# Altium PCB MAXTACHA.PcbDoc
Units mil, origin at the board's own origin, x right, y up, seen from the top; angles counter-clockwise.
Board outline 4035.43 x 2603.97 mil, 2 copper layers (Top Layer, Bottom Layer); 27 components, 20 nets, 75 pads, 0 vias.
Unrouted connection lines stored in the file: 14.
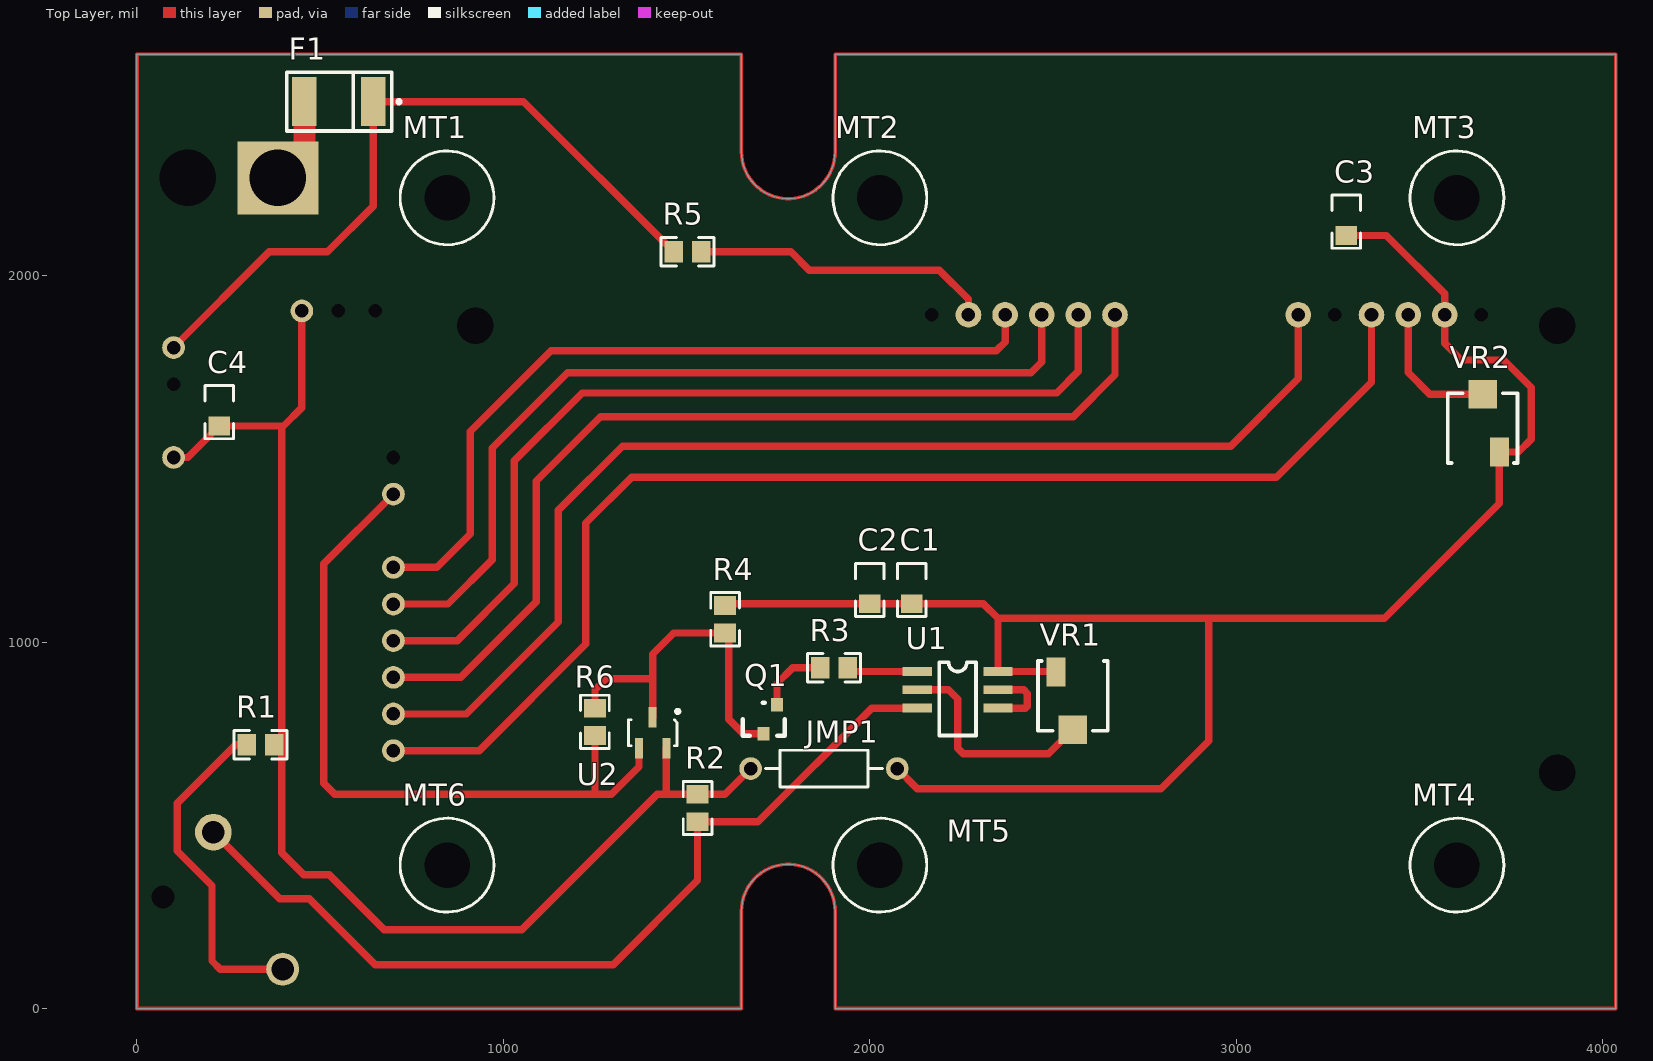
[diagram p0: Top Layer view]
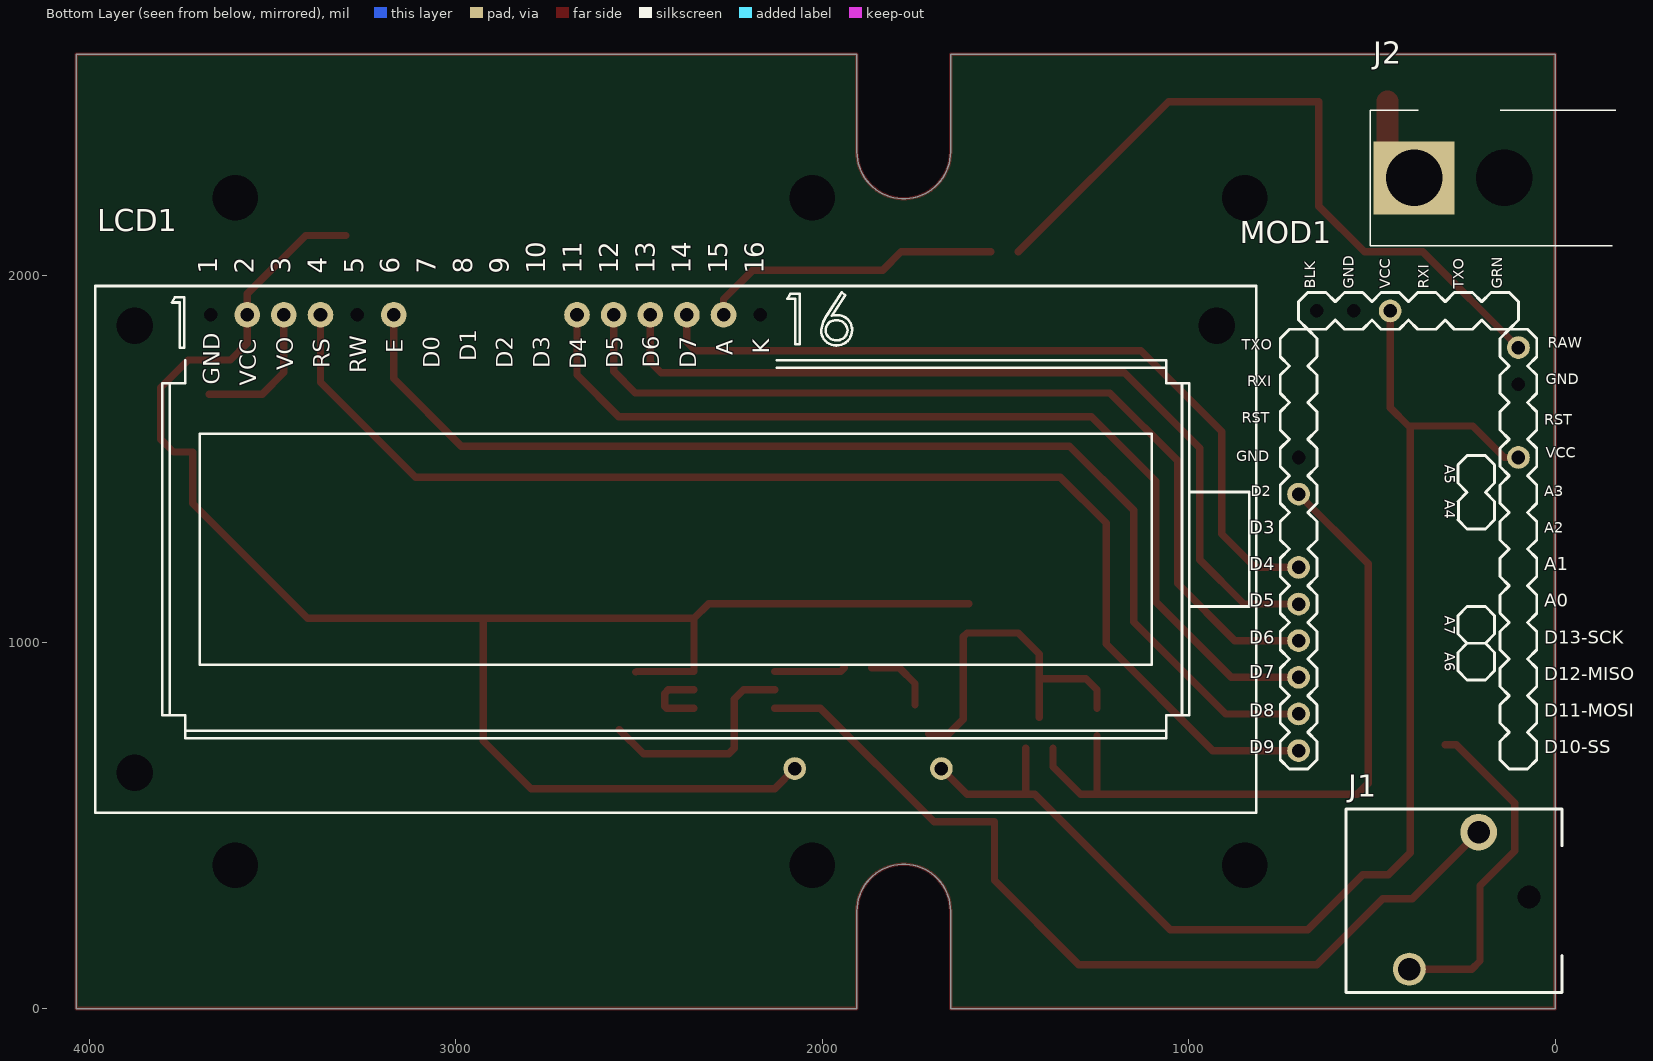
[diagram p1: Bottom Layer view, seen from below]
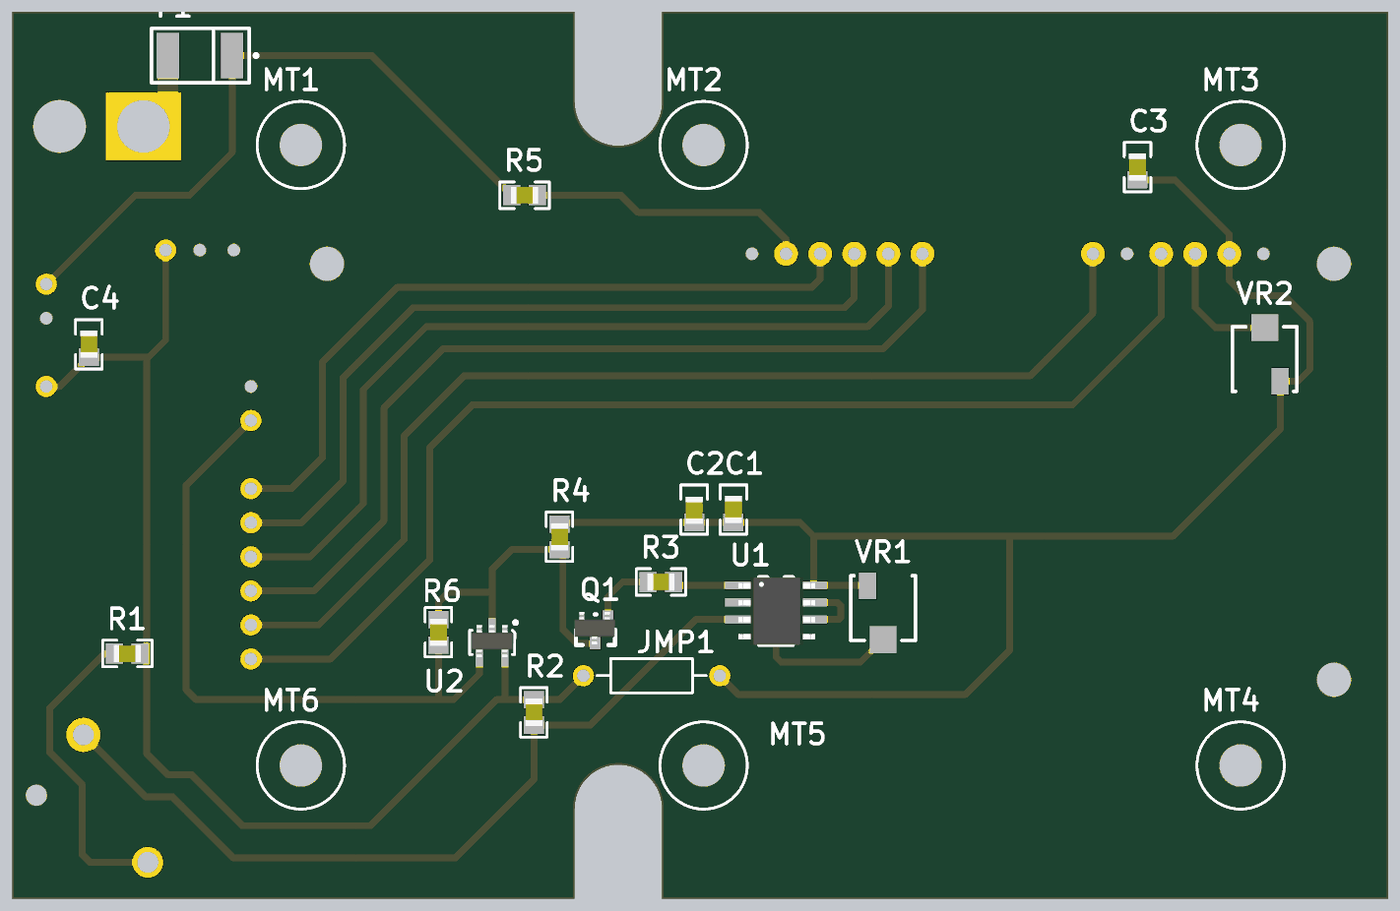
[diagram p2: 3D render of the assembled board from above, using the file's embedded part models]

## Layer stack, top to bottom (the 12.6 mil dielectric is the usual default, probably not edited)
Top Solder: solder mask 0.4, Solder Resist, Dk 3.5
Top Layer: signal copper 1.4
Dielectric1: dielectric 12.6, FR-4, Dk 4.8
Bottom Layer: signal copper 1.4
Bottom Solder: solder mask 0.4, Solder Resist, Dk 3.5

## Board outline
0,0 0,2603.97 1649.61,2603.97 1649.61,2338.18 ccw(c1777.56,2338.18) 1905.51,2338.18 1905.51,2603.97 4035.43,2603.97 4035.43,0 1905.51,0 1905.51,265.8 ccw(c1777.56,265.8) 1649.61,265.8 1649.61,0

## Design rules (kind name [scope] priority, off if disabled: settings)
Clearance Clearance_4 [(IsPad AND NOT HasFootprint('*PROD*')) vs IsVia] p1: gap=1
Clearance Clearance_3 [(HasFootprint('MT*'))] p2: gap=30
Clearance Clearance_2 [(InPoly) vs (HasFootprint('PAD063')) And OnLayer(BottomLayer)] p3: gap=50
Clearance Clearance_1 [(InPoly) vs (IsPad)] p4: gap=25
Clearance [All] p5: gap=7
ComponentClearance [All] p1: gap=20 collisioncheckmode=3 verticalgap=10 showdistances=FALSE
DiffPairsRouting [All] p1: maxlimit=20 minlimit=7 mostfreqgap=8 toplayer_minwidth=7 toplayer_maxwidth=15 toplayer_prefwidth=8 bottomlayer_minwidth=7 bottomlayer_maxwidth=15 bottomlayer_prefwidth=8 maxuncoupledlength=500
FabricationTestPointUsage TestPointUsage [All] p1: valid=0 allowmultiple=FALSE
FabricationTestpoint Testpoint [All] p1: side=3 testpointundercomponent=TRUE minsize=40 maxsize=100 preferedsize=60 minholesize=0 maxholesize=40 preferedholesize=32 testpointgrid=1 allowsidetop=TRUE allowsidebottom=TRUE usegrid=TRUE gridtolerance=0.01
PlaneClearance [All] p1: clearance=12
PlaneConnect [All] p1: planeconnectstyle=Relief reliefexpansion=8 reliefentries=4 reliefconductorwidth=10 reliefairgap=8
PolygonConnect [IsVia] p1: connectstyle=Direct reliefconductorwidth=10 reliefentries=4 polygonreliefangle="90 Angle" airgapwidth=10
PolygonConnect PolygonConnect_2 [HasFootprint('MT*')] p2: connectstyle=Direct reliefconductorwidth=10 reliefentries=4 polygonreliefangle="90 Angle" airgapwidth=10
PolygonConnect PolygonConnect_1 [All] p3: connectstyle=Relief reliefconductorwidth=20 reliefentries=4 polygonreliefangle="90 Angle" airgapwidth=10
RoutingPriority [All] p1: routingpriority=1
RoutingVias [All] p1: holewidth=16 width=31 viastyle="Through Hole" minholewidth=16 minwidth=31 maxholewidth=16 maxwidth=31
SilkToSolderMaskClearance [IsPad] p1: minsilkscreentomaskgap=1 clearancetoexposedcopper=TRUE
SolderMaskExpansion SolderMaskExpansion_1 [(IsVia)] p1: expansion=-150
SolderMaskExpansion [All] p2: expansion=2
Width [All] p1: maxlimit=100 minlimit=7 preferedwidth=7
22 further rules are at their usual default settings.

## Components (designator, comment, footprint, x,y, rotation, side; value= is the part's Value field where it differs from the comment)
C1 "0.1UF-08" _0805#1 2115,1105 r90 top
C2 "10UF-08" 0805 2000,1105 r90 top
C3 "0.1UF-08" _0805#1 3300,2110 r90 top
C4 "0.1UF-08" _0805#1 225,1590 r90 top
F1 "PLYSWMINISMDC075" POLYMSMDC 645,2475 r180 top
J1 "CUI-SJ1-3515N" CUI-SJ1-3515N 70.87,304.25 r180 bottom locked
J2 "RAPC712" RAPC712 384.86,2266.97 r90 bottom
JMP1 "TH-P25WRES" TH-RP25 2075,655 r180 top
LCD1 "LCM-S01602DSF_A" LCM-S01602DSF_A 3669.33,1893.23 r180 bottom locked
MOD1 "ARDUINOPROMINI" ARDUINOPROMINI 400,1303.97 r180 bottom locked
MT1 "MTHOLE125" MT125 846.46,2212.42 r0 top
MT2 "MTHOLE125" MT125 2027.56,2212.42 r0 top
MT3 "MTHOLE125" MT125 3602.36,2212.42 r0 top
MT4 "MTHOLE125" MT125 3602.36,391.55 r0 top
MT5 "MTHOLE125" MT125 2027.56,391.55 r0 top
MT6 "MTHOLE125" MT125 846.46,391.55 r0 top
Q1 "MMBT3904" SOT-23 1710,750 r180 top
R1 "150R-08" _0805#2 300,720 r0 top
R2 "470K-08" _0805#2 1530,510 r90 top
R3 "1K-08" _0805#2 1865,930 r0 top
R4 "10K-08" _0805#2 1605,1025 r90 top
R5 "120R-08" _0805#2 1465,2065 r0 top
R6 "0R-08" _0805#2 1250,745 r90 top
U1 "LT1211" SO-8 2130,920 r0 top
U2 "NP-SN74LVC1G14DBVR" SOT23-5 1445,795 r180 top
VR1 "BOU3314J-20K" BOU-3314J 2553.77,839.73 r180 top
VR2 "BOU3314J-20K" BOU-3314J 3673.11,1597.86 r0 top

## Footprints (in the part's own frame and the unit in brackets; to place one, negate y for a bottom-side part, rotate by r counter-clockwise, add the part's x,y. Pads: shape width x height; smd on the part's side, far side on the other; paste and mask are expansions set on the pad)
0805 [mm]
  rect 1.3x1.5 smd: 1(0,0)
  silkscreen extent -0.89,-0.99 2.79,0.99, body extent -0.1,-0.64 1.92,0.64, height 0.62
_0805#1 [mm]
  rect 1.3x1.5 smd: 1(0,0)
  silkscreen extent -0.89,-0.99 2.79,0.99, body extent -0.05,-0.64 1.97,0.64, height 0.62
_0805#2 [mm]
  rect 1.3x1.5 smd: 1(0,0) 2(1.9,0)
  silkscreen extent -0.89,-0.99 2.79,0.99, body extent -0.05,-0.64 1.97,0.64, height 0.62
ARDUINOPROMINI [mil] "FOOTPRINT FOR ARDUINO PRO MINI"
  round 62 hole 37: 104(-50,600) 601(300,500) 604(300,200) 701(-300,-600) 702(-300,-500) 703(-300,-400) 704(-300,-300) 705(-300,-200) 706(-300,-100) 708(-300,100)
  round 0 hole 37: 105(-150,600) 106(-250,600) 602(300,400) 709(-300,200)
  silkscreen extent -350,-650 350,650
BOU-3314J [mm]
  rect 1.3x2 smd: 1(1.15,-2)
  rect 2x2 smd: 2(0,2)
  silkscreen extent -2.42,-2.76 2.41,2.06
CUI-SJ1-3515N [mil] "CUI 3.5MM AUDIO SAME AS RS 274-0246"
  rect 0x0 hole 62: 1(0,0)
  round 100 hole 62: 2(-137.8,177.17)
  round 90 hole 62: 3(-326.77,-196.85)
  silkscreen extent -500,-260 90,240
LCM-S01602DSF_A [mil] "LUMEX 16X2 LCD MODULE LED BKLITE"
  rect 0x0 hole 37: 1(0,0)
  round 70 hole 37: 2(100,0) 3(200,0) 4(300,0) 6(500,0) 11(1000,0) 12(1100,0) 13(1200,0) 14(1300,0) 15(1400,0)
  round 0 hole 37: 5(400,0) 16(1500,0)
  round 0 hole 100: MT1(-206.69,-29.53) MT2(-206.69,-1250) MT4(2746.06,-29.53)
  silkscreen extent -315,-1358 2854,79
MT125 [mil]
  round 0 hole 124: 1(0,0)
  silkscreen extent -128,-128 128,128
POLYMSMDC [mm]
  rect 1.68x3.4 smd: 1(0,0) 2(4.78,0)
  silkscreen extent -1.91,-2.03 6,2.03
RAPC712 [mil]
  rect 200x220 hole 154: 1(0,0)
  round 0 hole 154: 3(0,-246)
  silkscreen extent -185,-550 185,119
SO-8 [mil]
  rect 80x24 smd: 1(0,0) 2(0,-50) 3(0,-100) 6(220,-100) 7(220,-50) 8(220,0)
  silkscreen extent 60,-175 160,25, body extent 0,-174 224,23, height 65
SOT23-5 [mm] "SOT-23/SC-74A; 5 Leads; Body 3 x 3 mm, inc. leads (LxW max)"
  rect 0.55x1.45 smd: 2(0.95,0) 4(1.9,2.15) 5(0,2.15)
  silkscreen extent -0.91,-0.53 2.63,1.98, body extent -0.55,-0.23 2.45,2.17, height 1.15
SOT-23 [mil]
  rect 32x36 smd: 1(-37,-79) 3(0,0)
  silkscreen extent -58,-85 57,5, body extent -57,-92 61,2, height 45
TH-RP25 [mil]
  round 62 hole 37: 1(0,0) 2(400,0)
  silkscreen extent 40,-50 360,50

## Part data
C1 C3 C4: library part 0CAP-08
C2: library part .01UF-06
F1: "POLYSWITCH 075"
J1: "CUI 3.5MM TRS STEREO AUDIO SAME AS RS 274-0246"
J2: "SWCRFT DC PWR .1 PCB RGT ANG MATES WITH 760"
JMP1: "RESISTOR 1/4W"
LCD1: "LUMEX 16X2 LCD MODULE LED BKLITE"
R1 R2 R3 R4 R5 R6: library part 0805R
U2: library part SN74LVC1G14DBVR, "TI SCHMITT TRIG INV  296-11607-1-ND"
VR1 VR2: library part BOU3314J, "BOURNS 3314J 4MM TRIMMER"

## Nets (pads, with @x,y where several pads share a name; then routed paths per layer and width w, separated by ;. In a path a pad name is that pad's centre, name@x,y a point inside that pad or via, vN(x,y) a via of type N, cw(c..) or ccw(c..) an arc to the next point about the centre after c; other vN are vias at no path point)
EN: LCD1.6 MOD1.702 | length 3201.1
  Top Layer w20: MOD1.702 898.97,803.97 1150,1055 1150,1360 1325,1535 2985,1535 3169.33,1719.33 LCD1.6
GND: J1.1 J2.3 LCD1.1 LCD1.5 LCD1.16 MOD1.105 MOD1.106 MOD1.602 MOD1.709 MT1.1 MT2.1 MT3.1 MT4.1 MT5.1 MT6.1
LCD_D4: LCD1.11 MOD1.703 | length 2668.4
  Top Layer w20: MOD1.703 883.97,903.97 1090,1110 1090,1440 1265,1615 2555,1615 2669.33,1729.33 LCD1.11
LCD_D5: LCD1.12 MOD1.704 | length 2524.1
  Top Layer w20: MOD1.704 873.97,1003.97 1030,1160 1030,1495 1215,1680 2510,1680 2569.33,1739.33 LCD1.12
LCD_D6: LCD1.13 MOD1.705 | length 2350.4
  Top Layer w20: MOD1.705 848.97,1103.97 970,1225 970,1530 1175,1735 2440,1735 2469.33,1764.33 LCD1.13
LCD_D7: LCD1.14 MOD1.706 | length 2162.1
  Top Layer w20: MOD1.706 818.97,1203.97 910,1295 910,1575 1130,1795 2345,1795 2369.33,1819.33 LCD1.14
NetF1_2: F1.2 J2.1 | length 237.8
  Top Layer w60: J2.1 456.81,2338.93 F1.2
NetJ1_2: J1.2 R2.1 U1.3 | length 2454.7
  Top Layer w20: J1.2 390.08,300 470,300 650,120 1300,120 1530,350 R2.1 1695,510 2005,820 U1.3
NetJ1_3: J1.3 R1.1 | length 927.6
  Top Layer w20: R1.1 270,720 110,560 110,430 205,335 205,130 227.6,107.4 J1.3
NetLCD1_3: LCD1.3 VR2.2 | length 385.8
  Top Layer w20: LCD1.3 3469.33,1735.67 3528.4,1676.6 VR2.2
NetLCD1_15: LCD1.15 R5.2 | length 825.5
  Top Layer w20: R5.2 1785,2065 1835,2015 2190,2015 2269.33,1935.67 LCD1.15
NetMOD1_708: MOD1.708 R6.1 U2.4 | length 1981.6
  Top Layer w20: MOD1.708 510,1213.97 510,615 540,585 1250,585 ; R6.1 1250,585 ; U2.4 1370.2,660.2 1295,585 1250,585
NetQ1_1: Q1.1 R3.1 | length 193.8
  Top Layer w20: Q1.1 1747,887 1790,930 R3.1
NetQ1_3: Q1.3 R4.1 R6.2 U2.2 | length 964.7
  Top Layer w20: R6.2 1250,870 1280,900 1407.6,900 ; U2.2 1407.6,900 ; Q1.3 1655,750 1615,790 1615,1015 R4.1 1465,1025 1407.6,967.6 1407.6,900
NetR3_2: R3.2 U1.1 | length 194.3
  Top Layer w20: R3.2 1949.8,920 U1.1
NetU1_2: U1.2 VR1.2 | length 602.7
  Top Layer w20: U1.2 2215,870 2240,845 2240,710 2255,695 2487.78,695 VR1.2
NetU1_6: U1.6 U1.7 | length 201.2
  Top Layer w20: U1.6 2425,820 2430,825 2430,860 2420,870 U1.7
RS: LCD1.4 MOD1.701 | length 3463
  Top Layer w20: MOD1.701 933.97,703.97 1225,995 1225,1325 1350,1450 3110,1450 3369.33,1709.33 LCD1.4
VCC: C1.1 C2.1 C3.1 C4.1 JMP1.1 JMP1.2 LCD1.2 MOD1.104 MOD1.604 R1.2 R2.2 R4.2 U1.8 U2.5 VR1.1 VR2.1 | length 8481.7
  Top Layer w20: MOD1.604 138.97,1503.97 C4.1 400,1590 ; MOD1.104 450,1640 400,1590 ; U2.5 1445,585 ; R4.2@1600,1105 C2.1 C1.1 2310,1105 2350,1065 ; JMP1.2 1604.8,584.8 R2.2 1529.8,585 1445,585 ; JMP1.1 2130,600 2795,600 2925,730 2925,1065 ; VR1.1 2506.97,920 U1.8 2350,1065 ; C3.1 3410,2110 3569.33,1950.67 LCD1.2 3569.33,1815.67 3615,1770 3730,1770 3805,1695 3805,1553.48 3770.64,1519.12 VR2.1 3718.39,1378.39 3405,1065 2925,1065 ; 400,1590 395,1585 395,425 455,365 525,365 675,215 1050,215 1420,585 1445,585 ; 2350,1065 2925,1065
VIN: F1.1 MOD1.601 R5.1 | length 1979.7
  Top Layer w20: MOD1.601 361.03,2065 520,2065 645,2190 F1.1 1055,2475 R5.1
pads on no net: LCD1.MT1 LCD1.MT2 LCD1.MT4
copper on no net: | length 14634.1
  Top Layer w10: 0,0 1649.61,0 1649.61,265.8 cw(c1777.56,265.8) 1905.51,265.8 1905.51,0 4035.43,0 4035.43,2603.97 1905.51,2603.97 1905.51,2338.18 cw(c1777.56,2338.18) 1649.61,2338.18 1649.61,2603.97 0,2603.97 0,0

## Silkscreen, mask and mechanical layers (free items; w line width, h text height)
Mechanical 4:
  the board outline again, w5
Mechanical 6:
  rectangle: 1325,835 1370,950
  text "0R 1206" at 1370,970 h50 r90
Mechanical 10:
  drawing of 646 lines, arcs and shapes, not listed
Mechanical 11:
  drawing of 3794 lines, arcs and shapes, not listed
